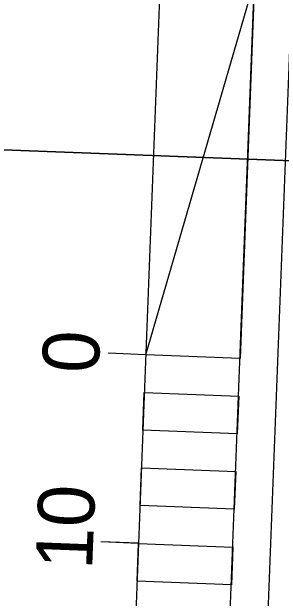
# Model space of a CAD drawing. Extents: x 2097431 to 2097897, y 685861 to 686794.
# Drawn here: x 2097487.64 to 2097501.92, y 686623.59 to 686654.67 of the extents above; entities that cross this region are included whole.
import ezdxf

# ---------------------------------------------------------------- set-up
doc = ezdxf.new("R2010")
doc.units = 0
for name, color, linetype in [('Scratch_Level_5', 7, 'Continuous'), ('Sheet Data Field CELL', 7, 'Continuous'), ('Sheet Plan And Profile CELL', 7, 'Continuous'), ('Sheet Title CELL', 7, 'Continuous')]:
    doc.layers.add(name, color=color, linetype=linetype)

msp = doc.modelspace()

# ---------------------------------------------------------------- linework, layer by layer
at = {"layer": 'Scratch_Level_5'}
msp.add_lwpolyline([(2097443.756, 686088.61), (2097699.444, 686078.804), (2097722.438, 686678.363), (2097503.654, 686686.754), (2097500.587, 686606.792), (2097463.684, 686608.208)], close=True, dxfattribs=at)
at = {"layer": 'Sheet Data Field CELL'}
msp.add_line((2097494.355, 686626.506), (2097492.357, 686626.582), dxfattribs=at)
at = {"layer": 'Sheet Plan And Profile CELL'}
msp.add_line((2097480.226, 686647.623), (2097525.173, 686645.899), dxfattribs=at)
for points in [[(2097480.226, 686647.623), (2097481.759, 686687.593), (2097526.726, 686685.869), (2097525.193, 686645.898)], [(2097478.693, 686607.632), (2097480.226, 686647.623), (2097525.193, 686645.898), (2097523.66, 686605.907)]]:
    msp.add_lwpolyline(points, close=True, dxfattribs=at)
at = {"layer": 'Sheet Title CELL'}
for p, q in [((2097496.271, 686676.464), (2097493.972, 686616.508)), ((2097498.968, 686616.316), (2097501.273, 686676.272)), ((2097494.743, 686636.493), (2097492.745, 686636.57)), ((2097494.509, 686630.498), (2097499.505, 686630.306)), ((2097494.36, 686626.501), (2097492.357, 686626.577))]:
    msp.add_line(p, q, dxfattribs=at)
for points in [[(2097494.743, 686636.493), (2097500.501, 686656.287), (2097499.74, 686636.302)], [(2097494.585, 686632.496), (2097494.662, 686634.495), (2097499.663, 686634.303), (2097499.582, 686632.305)], [(2097494.437, 686628.499), (2097494.509, 686630.498), (2097499.505, 686630.306), (2097499.428, 686628.308)], [(2097494.284, 686624.502), (2097494.36, 686626.501), (2097499.352, 686626.309), (2097499.275, 686624.311)]]:
    msp.add_lwpolyline(points, close=True, dxfattribs=at)

# ---------------------------------------------------------------- texts
at = {"layer": 'Sheet Data Field CELL'}
msp.add_text('10', height=3, rotation=87.8037, dxfattribs=at).set_placement((2097491.899, 686625.085))
at = {"layer": 'Sheet Title CELL'}
msp.add_text('0', height=3, rotation=87.8037, dxfattribs=at).set_placement((2097492.243, 686635.488))

doc.saveas('drawing.dxf')
